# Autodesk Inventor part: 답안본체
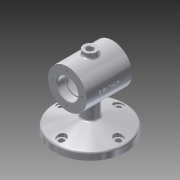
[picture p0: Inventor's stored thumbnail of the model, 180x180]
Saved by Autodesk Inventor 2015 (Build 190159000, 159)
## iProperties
Created: 2018-12
Part Number: 답안본체
Material: 알루미늄 6061
Document SubType Name: Modeling
Designer: now060
Density: 2.7 g/cm^3
Appearance: 알루미늄 - 평지
Mass: 685.037 g
Surface Area: 554.996 cm^2
Volume: 253.717 cm^3
Author: now060
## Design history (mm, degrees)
sketch "스케치7"
  geometry: C1 r 55 at (0, 0); 1 further point
  constraints: 1 centre point, 1 coincident
  dimensions: "d19" = 110 diameter of C1
extrude "돌출2" new body sketch "스케치7" distance "d20" = 11; taper "d21" = 0 deg
sketch "스케치8"
  geometry: C1 r 55 at (0, 0) reference; C2 r 12 at (0, 0)
  constraints: 1 centre point, 1 coincident
  dimensions: "d22" = 24 diameter of C2
extrude "돌출3" join sketch "스케치8" distance "d23" = 65; taper "d24" = 0 deg
sketch "스케치9"
  geometry: L1 (55, 11)-(55, 0) reference; L2 (55, 0)-(-55, 0) reference; L3 (-55, 0)-(-55, 11) reference; L4 (-55, 11)-(-12, 11) reference; L5 (-12, 11)-(-12, 76) reference; L6 (-12, 76)-(12, 76) reference; L7 (12, 76)-(12, 11) reference; L8 (12, 11)-(55, 11) reference; L9 (-35, 75)-(35, 75); L10 (35, 75)-(35, 105); L11 (35, 105)-(-35, 105); L12 (-35, 105)-(-35, 75); 3 further points
  constraints: 8 end point, 3 perpendicular, 2 midpoint, 1 horizontal, 1 vertical alignment
  dimensions: "d25" = 30 distance of L9.end L10.end; "d26" = 70 distance of L10.end L11.end; "d27" = 75 distance from line of L9 point (0, 0)
revolve "회전5" sketch "스케치9" stored, may be unused: angle "d28" = 90 deg
sketch "스케치10"
  geometry: L1 (55, 11)-(55, 0) reference; L2 (55, 0)-(-55, 0) reference; L3 (-55, 0)-(-55, 11) reference; L4 (-55, 11)-(-12, 11) reference; L5 (-12, 11)-(-12, 45) reference; L6 (-12, 45)-(-35, 45) reference; L7 (-35, 45)-(-35, 105) reference; L8 (-35, 105)-(35, 105) reference; L9 (35, 105)-(35, 45) reference; L10 (35, 45)-(12, 45) reference; L11 (12, 45)-(12, 11) reference; L12 (12, 11)-(55, 11) reference; L13 (-35, 45)-(-35, 105) reference; L14 (-35, 75)-(-23, 75); L15 (-23, 75)-(-23, 90.7); L16 (-23.3, 91)-(-35, 91); L17 (-35, 91)-(-35, 75); A1 r 0.3 centre (-23.3, 90.7) between (-23, 90.7) and (-23.3, 91); 2 further points
  constraints: 8 end point, 2 parallel, 2 point on circle, 2 point on line, 2 tangent, 1 centre point, 1 horizontal, 1 midpoint, 1 perpendicular
  dimensions: "d29" = 12 distance of point (-23, 91) L16.end; "d30" = 16 distance of L14.end point (-23, 91); "d31" = 0.3 radius of A1
revolve "회전6" sketch "스케치10" stored, may be unused: angle "d32" = 90 deg
sketch "스케치11"
  geometry: L1 (55, 11)-(55, 0) reference; L2 (55, 0)-(-55, 0) reference; L3 (-55, 0)-(-55, 11) reference; L4 (-55, 11)-(-12, 11) reference; L5 (-12, 11)-(-12, 45) reference; L6 (-12, 45)-(-35, 45) reference; L7 (-35, 45)-(-35, 59) reference; L8 (-35, 59)-(-23.3, 59) reference; L9 (-23, 59.3)-(-23, 90.7) reference; L10 (-23.3, 91)-(-35, 91) reference; L11 (-35, 91)-(-35, 105) reference; L12 (-35, 105)-(35, 105) reference; L13 (35, 105)-(35, 45) reference; L14 (35, 45)-(12, 45) reference; L15 (12, 45)-(12, 11) reference; L16 (12, 11)-(55, 11) reference; L17 (-23, 75)-(-20, 75); L18 (-20, 75)-(-20, 89); L19 (-20, 89)-(-23, 89); L20 (-23, 89)-(-23, 75); A1 r 0.3 centre (-23.3, 59.3) between (-23.3, 59) and (-23, 59.3) reference; A2 r 0.3 centre (-23.3, 90.7) between (-23, 90.7) and (-23.3, 91) reference; 1 further point
  constraints: 8 end point, 2 parallel, 1 horizontal, 1 midpoint, 1 perpendicular
  dimensions: "d33" = 3 distance of L18.end L19.end; "d34" = 14 distance of L17.end L18.end
revolve "회전7" sketch "스케치11" stored, may be unused: angle "d35" = 90 deg
sketch "스케치12"
  geometry: L1 (55, 11)-(55, 0) reference; L2 (55, 0)-(-55, 0) reference; L3 (-55, 0)-(-55, 11) reference; L4 (-55, 11)-(-12, 11) reference; L5 (-12, 11)-(-12, 45) reference; L6 (-12, 45)-(-35, 45) reference; L7 (-35, 45)-(-35, 59) reference; L8 (-35, 59)-(-23.3, 59) reference; L9 (-23, 59.3)-(-23, 61) reference; L10 (-23, 61)-(-20, 61) reference; L11 (-20, 61)-(-20, 89) reference; L12 (-20, 89)-(-23, 89) reference; L13 (-23, 89)-(-23, 90.7) reference; L14 (-23.3, 91)-(-35, 91) reference; L15 (-35, 91)-(-35, 105) reference; L16 (-35, 105)-(35, 105) reference; L17 (35, 105)-(35, 45) reference; L18 (35, 45)-(12, 45) reference; L19 (12, 45)-(12, 11) reference; L20 (12, 11)-(55, 11) reference; L21 (-20, 75)-(20, 75); L22 (20, 75)-(20, 97); L23 (17, 100)-(-17, 100); L24 (-20, 97)-(-20, 75); A1 r 0.3 centre (-23.3, 59.3) between (-23.3, 59) and (-23, 59.3) reference; A2 r 0.3 centre (-23.3, 90.7) between (-23, 90.7) and (-23.3, 91) reference; A3 r 3 centre (-17, 97) between (-17, 100) and (-20, 97); A4 r 3 centre (17, 97) between (20, 97) and (17, 100); 3 further points
  constraints: 8 end point, 4 point on circle, 4 point on line, 4 tangent, 2 centre point, 2 parallel, 1 equal radius, 1 horizontal, 1 midpoint, 1 perpendicular
  dimensions: "d36" = 40 distance of point (20, 100) point (-20, 100); "d37" = 25 distance of L21.end point (20, 100); "d38" = 3 radius of A3
revolve "회전8" sketch "스케치12" stored, may be unused: angle "d39" = 90 deg
sketch "스케치13"
  geometry: L1 (55, 11)-(55, 0) reference; L2 (55, 0)-(-55, 0) reference; L3 (-55, 0)-(-55, 11) reference; L4 (-55, 11)-(-12, 11) reference; L5 (-12, 11)-(-12, 45) reference; L6 (-12, 45)-(-35, 45) reference; L7 (-35, 45)-(-35, 59) reference; L8 (-35, 59)-(-23.3, 59) reference; L9 (-23, 59.3)-(-23, 61) reference; L10 (-23, 61)-(-20, 61) reference; L11 (-20, 61)-(-20, 53) reference; L12 (-17, 50)-(17, 50) reference; L13 (20, 53)-(20, 97) reference; L14 (17, 100)-(-17, 100) reference; L15 (-20, 97)-(-20, 89) reference; L16 (-20, 89)-(-23, 89) reference; L17 (-23, 89)-(-23, 90.7) reference; L18 (-23.3, 91)-(-35, 91) reference; L19 (-35, 91)-(-35, 105) reference; L20 (-35, 105)-(35, 105) reference; L21 (35, 105)-(35, 45) reference; L22 (35, 45)-(12, 45) reference; L23 (12, 45)-(12, 11) reference; L24 (12, 11)-(55, 11) reference; L25 (20, 75)-(23, 75); L26 (23, 75)-(23, 89); L27 (23, 89)-(20, 89); L28 (20, 89)-(20, 75); A1 r 0.3 centre (-23.3, 59.3) between (-23.3, 59) and (-23, 59.3) reference; A2 r 3 centre (-17, 53) between (-20, 53) and (-17, 50) reference; A3 r 3 centre (17, 53) between (17, 50) and (20, 53) reference; A4 r 3 centre (17, 97) between (20, 97) and (17, 100) reference; A5 r 3 centre (-17, 97) between (-17, 100) and (-20, 97) reference; A6 r 0.3 centre (-23.3, 90.7) between (-23, 90.7) and (-23.3, 91) reference; 1 further point
  constraints: 8 end point, 2 parallel, 1 horizontal, 1 midpoint, 1 perpendicular
  dimensions: "d40" = 3 distance of L26.end L27.end; "d41" = 14 distance of L25.end L26.end
revolve "회전9" sketch "스케치13" stored, may be unused: angle "d42" = 90 deg
sketch "스케치14"
  geometry: L1 (55, 11)-(55, 0) reference; L2 (55, 0)-(-55, 0) reference; L3 (-55, 0)-(-55, 11) reference; L4 (-55, 11)-(-12, 11) reference; L5 (-12, 11)-(-12, 45) reference; L6 (-12, 45)-(-35, 45) reference; L7 (-35, 45)-(-35, 59) reference; L8 (-35, 59)-(-23.3, 59) reference; L9 (-23, 59.3)-(-23, 61) reference; L10 (-23, 61)-(-20, 61) reference; L11 (-20, 61)-(-20, 53) reference; L12 (-17, 50)-(17, 50) reference; L13 (20, 53)-(20, 61) reference; L14 (20, 61)-(23, 61) reference; L15 (23, 61)-(23, 89) reference; L16 (23, 89)-(20, 89) reference; L17 (20, 89)-(20, 97) reference; L18 (17, 100)-(-17, 100) reference; L19 (-20, 97)-(-20, 89) reference; L20 (-20, 89)-(-23, 89) reference; L21 (-23, 89)-(-23, 90.7) reference; L22 (-23.3, 91)-(-35, 91) reference; L23 (-35, 91)-(-35, 105) reference; L24 (-35, 105)-(35, 105) reference; L25 (35, 105)-(35, 45) reference; L26 (35, 45)-(12, 45) reference; L27 (12, 45)-(12, 11) reference; L28 (12, 11)-(55, 11) reference; L29 (23, 89)-(23, 61) reference; L30 (23, 75)-(35, 75); L31 (35, 75)-(35, 91); L32 (35, 91)-(23.3, 91); L33 (23, 90.7)-(23, 75); A1 r 0.3 centre (-23.3, 59.3) between (-23.3, 59) and (-23, 59.3) reference; A2 r 3 centre (-17, 53) between (-20, 53) and (-17, 50) reference; A3 r 3 centre (17, 53) between (17, 50) and (20, 53) reference; A4 r 3 centre (17, 97) between (20, 97) and (17, 100) reference; A5 r 3 centre (-17, 97) between (-17, 100) and (-20, 97) reference; A6 r 0.3 centre (-23.3, 90.7) between (-23, 90.7) and (-23.3, 91) reference; A7 r 0.3 centre (23.3, 90.7) between (23.3, 91) and (23, 90.7); 2 further points
  constraints: 8 end point, 2 parallel, 2 point on circle, 2 point on line, 2 tangent, 1 centre point, 1 horizontal, 1 midpoint, 1 perpendicular
  dimensions: "d43" = 12 distance of L31.end point (23, 91); "d44" = 16 distance of point (23, 91) L30.start; "d45" = 0.3 radius of A7
revolve "회전10" sketch "스케치14" stored, may be unused: angle "d46" = 90 deg
sketch "스케치15" dims "d47" = 46
  geometry: C1 r 30 at (0, 0) reference; 3 further points
  constraints: 1 coincident, 1 vertical alignment, 2 other
hole "구멍1" sketch "스케치15" at (0, 23) diameter "d48" = 3.242; stored, may be unused: countersink angle "d52" = 90 deg, drill point angle "d54" = 118 deg; dims "d49" = 8, "d50" = 4, "d51" = 2, "d53" = 10
node "작업 평면1"
sketch "스케치16"
  geometry: C1 r 10 at (0, 0); 1 further point
  constraints: 1 centre point, 1 coincident
  dimensions: "d59" = 20 diameter of C1
extrude "돌출4" join sketch "스케치16" stored distance "d60" = 65; taper "d61" = 0 deg
sketch "스케치17"
  geometry: C1 r 10 at (0, 0) reference; C2 r 5 at (0, 0)
  constraints: 1 centre point, 1 coincident
  dimensions: "d62" = 10 diameter of C2
extrude "돌출5" cut sketch "스케치17" stored distance "d63" = 65; taper "d64" = 0 deg
fillet "모깎기1" dims "d65" = 3
chamfer "모따기1" distance "d66" = 1; stored, may be unused: second distance "d67" = 2, angle "d68" = 45 deg
node "작업축1"
sketch "스케치18"
  geometry: L1 (55, 11)-(-55, 11) reference; L2 (-55, 0)-(55, 0) reference; L3 (55, 11)-(-55, 11) reference; L4 (-55, 0)-(-55, 11) reference; L5 (0, 0)-(0, 112.228); L6 (-55, 11)-(0, 25.737); L7 (-55, 11)-(0, 11); L8 (0, 25.737)-(0, 11); L9 (0, 134.674)-(0, -22.446) reference
  constraints: 8 end point, 2 point on line, 2 vertical, 1 midpoint
  dimensions: "d70" = 75 deg angle of L4 L6
revolve "회전11" sketch "스케치18" stored, may be unused: angle "d71" = 90 deg
sketch "스케치19" dims "d72" = 88
  geometry: C1 r 55 at (0, 0) reference; C2 r 4.5 at (-44, 0); 1 further point
  constraints: 1 centre point, 1 coincident, 1 horizontal alignment, 2 other
  dimensions: "d73" = 9 diameter of C2
extrude "돌출6" cut sketch "스케치19" distance "d74" = 10; taper "d75" = 0 deg
sketch "스케치20"
  geometry: C1 r 4.5 at (0, 0) reference; C2 r 7 at (0, 0); 1 further point
  constraints: 1 centre point, 1 coincident
  dimensions: "d76" = 14 diameter of C2
extrude "돌출7" cut sketch "스케치20" distance "d77" = 10; taper "d78" = 0 deg
fillet "모깎기2" dims "d82" = 3
fillet "모깎기3" dims "d83" = 3
node "작업 평면2"
sketch "스케치21"
  geometry: L1 (-35, 45)-(-35, 105) reference; 2 further points
  constraints: 1 other
  dimensions: "d85" = 35 distance from line of L1 point (0, 75); "d86" = 30 vertical distance of L1.end point (0, 75)
feature "엠보싱1" sketch "스케치21" dims "d20" = 11, "d21" = 0, "d87" = 0.5, "d88" = 0
node "솔리드2"
pattern_circular "원형 패턴1" dims angle "d56" = 360 deg
mirror "대칭1"
pattern_circular "원형 패턴2" dims angle "d80" = 360 deg
node "투영된 루프1"
node "절단 모서리 투영6"
node "절단 모서리 투영7"
node "절단 모서리 투영8"
node "절단 모서리 투영9"
node "절단 모서리 투영10"
node "절단 모서리 투영11"
other parameters: "d58" = 112, "d84" = 31.25
